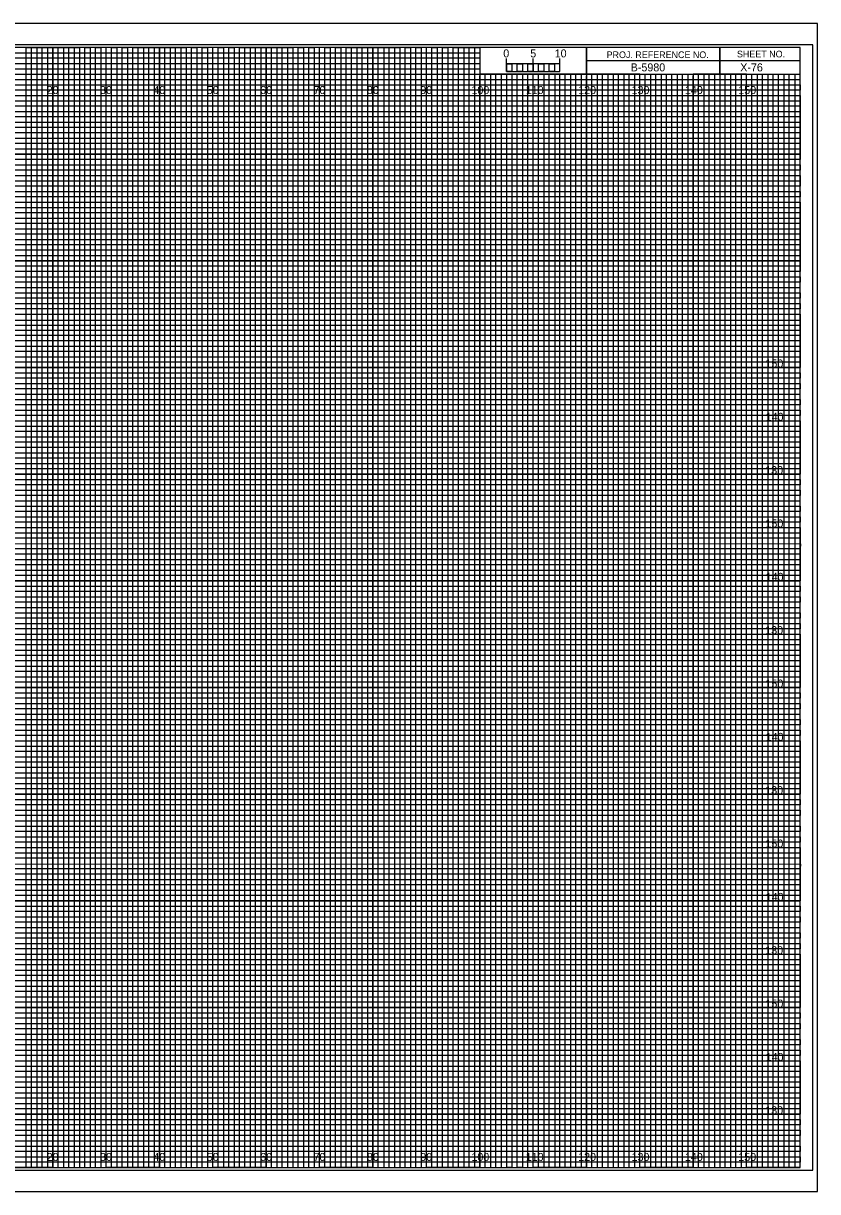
# Model space of a CAD drawing. Extents: x -13 to 323, y -5 to 654.
# Drawn here: x 174.5 to 323.3, y 435.5 to 654.5 of the extents above; entities that cross this region are included whole.
import ezdxf

# ---------------------------------------------------------------- set-up
doc = ezdxf.new("R2010")
doc.units = 0
for name, color, linetype in [('Exist Cross Section Cell', 7, 'Continuous'), ('Exist XS Center Line Elevation Label', 7, 'Continuous'), ('Exist XS Ground Line', 7, 'Continuous'), ('Prop CMT Guardrail Graphics', 7, 'Continuous'), ('Prop CMT Guardrail Widen Shoulder', 7, 'Continuous'), ('Prop CMT Pvmt Course 1', 7, 'Continuous'), ('Prop CMT Pvmt Course 2', 7, 'Continuous'), ('Prop CMT Pvmt Surface', 7, 'Continuous'), ('Prop CMT Shld Paved Course 1', 7, 'Continuous'), ('Prop CMT Shld Paved Course 2', 7, 'Continuous'), ('Prop CMT Shld Paved Course 3', 7, 'Continuous'), ('Prop CMT Slope Grass', 7, 'Continuous'), ('Prop CMT Subgrade Earthwork', 7, 'Continuous'), ('Prop Retaining Wall', 7, 'Continuous'), ('Prop XS Earthwork Shape', 7, 'Continuous')]:
    doc.layers.add(name, color=color, linetype=linetype)

msp = doc.modelspace()

# ---------------------------------------------------------------- linework, layer by layer
at = {"layer": 'Exist XS Center Line Elevation Label'}
for points in [[(165, 440), (175, 440), (175, 650), (185, 650), (185, 440), (195, 440), (195, 650), (205, 650), (205, 440), (215, 440), (215, 650), (225, 650), (225, 440), (235, 440), (235, 650), (245, 650), (245, 440), (255, 440), (255, 650), (259.93, 650), (260, 650), (260, 645), (264.99, 645), (264.99, 440), (275, 440), (275, 645), (285, 645), (285, 440), (295, 440), (295, 645), (305, 645), (305, 440), (315, 440), (315, 645)], [(0, 645), (275, 645)], [(0, 625), (320, 625), (320, 635), (0, 635)], [(0, 605), (320, 605), (320, 615), (0, 615)], [(0, 585), (320, 585), (320, 595), (0, 595)], [(0, 565), (320, 565), (320, 575), (0, 575)], [(0, 545), (320, 545), (320, 555), (0, 555)], [(0, 525), (320, 525), (320, 535), (0, 535)], [(0, 505), (320, 505), (320, 515), (0, 515)], [(0, 485), (320, 485), (320, 495), (0, 495)], [(0, 465), (320, 465), (320, 475), (0, 475)], [(0, 445), (320, 445), (320, 455), (0, 455)]]:
    msp.add_lwpolyline(points, dxfattribs=at)
at = {"layer": 'Exist XS Ground Line'}
for p, q in [((190, 650), (180, 650)), ((180, 650), (180, 440)), ((190, 440), (190, 650)), ((210, 650), (200, 650)), ((200, 650), (200, 440)), ((210, 440), (210, 650)), ((230, 650), (220, 650)), ((220, 650), (220, 440)), ((230, 440), (230, 650)), ((250, 650), (240, 650)), ((240, 650), (240, 440)), ((250, 440), (250, 650)), ((260, 650), (260, 440)), ((270, 440), (270, 645)), ((290, 645), (280, 645)), ((280, 645), (280, 440)), ((290, 440), (290, 645)), ((310, 645), (300, 645)), ((300, 645), (300, 440)), ((310, 440), (310, 645)), ((180, 440), (170, 440)), ((200, 440), (190, 440)), ((220, 440), (210, 440)), ((240, 440), (230, 440)), ((260, 440), (250, 440)), ((280, 440), (270, 440)), ((300, 440), (290, 440)), ((320, 440), (310, 440)), ((320, 440), (320, 440))]:
    msp.add_line(p, q, dxfattribs=at)
for points in [[(0, 640), (320, 640), (320, 630), (0, 630)], [(0, 620), (320, 620), (320, 610), (0, 610)], [(0, 600), (320, 600), (320, 590), (0, 590)], [(0, 580), (320, 580), (320, 570), (0, 570)], [(0, 560), (320, 560), (320, 550), (0, 550)], [(0, 540), (320, 540), (320, 530), (0, 530)], [(0, 520), (320, 520), (320, 510), (0, 510)], [(0, 500), (320, 500), (320, 490), (0, 490)], [(0, 480), (320, 480), (320, 470), (0, 470)], [(0, 460), (320, 460), (320, 450), (0, 450)]]:
    msp.add_lwpolyline(points, dxfattribs=at)
at = {"layer": 'Prop CMT Pvmt Course 1'}
for p, q in [((0, 649), (260, 649)), ((260, 649), (260, 647.98)), ((260, 647.98), (0, 647.98)), ((0, 647), (260, 647)), ((260, 647), (260, 645.89)), ((260, 645.89), (0, 645.89)), ((0, 644), (320, 644))]:
    msp.add_line(p, q, dxfattribs=at)
for points in [[(0, 643), (270, 643), (320, 643), (320, 642), (0, 642)], [(0, 641), (320, 641), (320, 639), (0, 639)], [(0, 638), (320, 638), (320, 637), (0, 636.98)], [(0, 636), (320, 636), (320, 634), (0, 634)], [(0, 633), (320, 633), (320, 632), (0, 632)], [(0, 631), (320, 631), (320, 629), (0, 629)], [(0, 628), (320, 628), (320, 627), (0, 627)], [(0, 626), (320, 626), (320, 624), (0, 624)], [(0, 623), (320, 623), (320, 622), (0, 622)], [(0, 621), (320, 621), (320, 619), (0, 619)], [(0, 618), (320, 618), (320, 617), (0, 617)], [(0, 616), (320, 616), (320, 613.95), (320, 613), (320, 612), (0, 612)], [(0, 614), (320, 614), (320, 613), (0, 613)], [(0, 611), (320, 611), (320, 609), (0, 609.03)], [(0, 609.03), (320, 609), (320, 608), (0, 608)], [(0, 607), (320, 607), (320, 606), (0, 606)], [(0, 604), (320, 604), (320, 603), (0, 603)], [(0, 602), (320, 602), (320, 601), (0, 601)], [(-0.07, 598.89), (320, 598.89), (320, 597.88), (-0.07, 597.88)], [(0, 597), (320, 597), (320, 596), (0, 596)], [(0, 594), (320, 594), (320, 593), (0, 593)], [(0, 592), (320, 592), (320, 591), (0, 591)], [(0, 589), (320, 589), (320, 588), (0, 588)], [(0, 587), (320, 587), (320, 586), (0, 586)], [(0, 584), (320, 584), (320, 583), (0, 583)], [(0, 582), (320, 582), (320, 581), (0, 581)], [(0, 579), (320, 579), (319.99, 577.98), (0, 578)], [(0, 577), (320, 577), (320, 576), (0, 576)], [(0, 574), (320, 574), (320, 573), (0, 573)], [(0, 572), (320, 572), (320, 571), (0, 571)], [(0, 569), (320, 569), (320, 568), (0, 568)], [(0, 567), (320, 567), (320, 566), (0, 566)], [(0, 564), (320, 564), (320, 563), (0, 563)], [(0, 562), (320, 562), (320, 561), (0, 561)], [(0, 559), (320, 559), (320, 558), (0, 558)], [(0, 556.99), (320.07, 556.91), (320, 556), (0, 556)], [(0, 554), (320, 554), (320, 553), (0, 553)], [(0, 552), (320, 552), (320, 551), (0, 551)], [(0, 549), (320, 549), (320, 548), (0, 548)], [(0, 547), (320, 547), (320, 546), (0, 546)], [(0, 544), (320, 544), (320, 543), (0, 543)], [(0, 542), (320, 542), (320, 541), (0, 541)], [(0, 539), (320, 539), (320, 538), (0, 538)], [(0, 537), (320, 537), (320, 536), (0, 536)], [(0, 534), (320, 534), (320, 533), (0, 533)], [(0, 532), (320, 532), (320, 531), (0, 531)], [(0, 529), (320, 529), (320, 528), (0, 528)], [(0, 527), (320, 527), (320, 526), (0, 526)], [(0, 524), (320, 524), (320, 523), (0, 523)], [(0, 522), (320, 522), (320, 521), (0, 521)], [(0, 519), (320, 519), (319.99, 517.98), (0, 518)], [(0, 517), (320, 517), (320, 516), (0, 516)], [(0, 514), (320, 514), (320, 513), (0, 513)], [(0, 512), (320, 512), (320, 511), (0, 511)], [(0, 509), (320, 509), (320, 508), (0, 508)], [(0, 507), (320, 507), (320, 506), (0, 506)], [(0, 504), (320, 504), (320, 503), (0, 503)], [(0, 502), (320, 502), (320, 501), (0, 501)], [(0, 499), (320, 499), (320, 498), (0, 498)], [(0, 496.99), (320.07, 496.91), (320, 496), (0, 496)], [(0, 494), (320, 494), (320, 493), (0, 493)], [(0, 492), (320, 492), (320, 491), (0, 491)], [(0, 489), (320, 489), (320, 488), (0, 488)], [(0, 487), (320, 487), (320, 486), (0, 486)], [(0, 484), (320, 484), (320, 483), (0, 483)], [(0, 482), (320, 482), (320, 481), (0, 481)], [(0, 479), (320, 479), (320, 478), (0, 478)], [(0, 477), (320, 477), (320, 476), (0, 476)], [(0, 474), (320, 474), (320, 473), (0, 473)], [(0, 472), (320, 472), (320, 471), (0, 471)], [(0, 469), (320, 469), (320, 468), (0, 468)], [(0, 467), (320, 467), (320, 466), (0, 466)], [(0, 464), (320, 464), (320, 463), (0, 463)], [(0, 462), (320, 462), (320, 461), (0, 461)], [(0, 459), (320, 459), (320, 458), (0, 458)], [(0, 457), (320, 457), (320, 456), (0, 456)], [(0, 454), (320, 454), (320, 453), (0, 453)], [(0, 452), (320, 452), (320, 451), (0, 451)], [(0, 449), (320, 449), (320, 448), (0, 448)], [(0, 447), (320, 447), (320, 446), (0, 446)], [(0, 444), (320, 444), (320, 443), (0, 443)], [(0, 442), (320, 442), (320, 441), (0, 441)]]:
    msp.add_lwpolyline(points, dxfattribs=at)
at = {"layer": 'Prop CMT Pvmt Surface'}
for p, q in [((267, 645), (266.01, 645)), ((266.01, 645), (266.01, 440)), ((267, 440), (267, 645)), ((269, 645), (268, 645)), ((268, 645), (268, 440)), ((269, 440), (269, 645)), ((266.01, 440), (265, 440)), ((268, 440), (267, 440))]:
    msp.add_line(p, q, dxfattribs=at)
for points in [[(175, 440), (176, 440), (176, 650), (177, 650), (177, 440)], [(177, 440), (178, 440), (178, 650), (179, 650), (179, 440)], [(180, 440), (181, 440), (181, 650), (182, 650), (182, 440)], [(182, 440), (183, 440), (183, 650), (184, 650), (184, 440)], [(185, 440), (186, 440), (186, 650), (187, 650), (187, 440)], [(187, 440), (188, 440), (188, 650), (189, 650), (189, 440)], [(190, 440), (191, 440), (191, 650), (192, 650), (192, 440)], [(192, 440), (193, 440), (193, 650), (194, 650), (194, 440)], [(195, 440), (196, 440), (196, 650), (197, 650), (197, 440)], [(197, 440), (198, 440), (198, 650), (199, 650), (199, 440)], [(200, 440), (201, 440), (201, 650), (202, 650), (202, 440)], [(202, 440), (203, 440), (203, 650), (204, 650), (204, 440)], [(205, 440), (206, 440), (206, 650), (207, 650), (207, 440)], [(207, 440), (208, 440), (208, 650), (209, 650), (209, 440)], [(210, 440), (211, 440), (211, 650), (212, 650), (212, 440)], [(212, 440), (213, 440), (213, 650), (214, 650), (214, 440)], [(215, 440), (216, 440), (216, 650), (217, 650), (217, 440)], [(217, 440), (218, 440), (218, 650), (219, 650), (219, 440)], [(220, 440), (221, 440), (221, 650), (222, 650), (222, 440)], [(222, 440), (223, 440), (223, 650), (224, 650), (224, 440)], [(225, 440), (226, 440), (226, 650), (227, 650), (227, 440)], [(227, 440), (228, 440), (228, 650), (229, 650), (229, 440)], [(230, 440), (231, 440), (231, 650), (232, 650), (232, 440)], [(232, 440), (233, 440), (233, 650), (234, 650), (234, 440)], [(235, 440), (236, 440), (236, 650), (237, 650), (237, 440)], [(237, 440), (238, 440), (238, 650), (239, 650), (239, 440)], [(240, 440), (241, 440), (241, 650), (242, 650), (242, 440)], [(242, 440), (243, 440), (243, 650), (244, 650), (244, 440)], [(245, 440), (246, 440), (246, 650), (247, 650), (247, 440)], [(247, 440), (248, 440), (248, 650), (249, 650), (249, 440)], [(250, 440), (251, 440), (251, 650), (252, 650), (252, 440)], [(252, 440), (253, 440), (253, 650), (254, 650), (254, 440)], [(255, 440), (256, 440), (256, 650), (257, 650), (257, 440)], [(257, 440), (258, 440), (258, 650), (259, 650), (259, 440)], [(260, 440), (261, 440), (261, 645), (262.02, 645), (262.02, 440)], [(262, 440), (263, 440), (263, 645), (263.99, 645), (263.99, 440)], [(270, 440), (270.98, 440), (270.98, 645), (272, 645), (272, 440)], [(272, 440), (273, 440), (273, 645), (274.05, 645), (274.05, 440)], [(275, 440), (276, 440), (276, 645), (277, 645), (277, 440)], [(277, 440), (278, 440), (278, 645), (279, 645), (279, 440)], [(280, 440), (281, 440), (281, 645), (282, 645), (282, 440)], [(282, 440), (283, 440), (283, 645), (284, 645), (284, 440)], [(285, 440), (286, 440), (286, 645), (287, 645), (287, 440)], [(287, 440), (288, 440), (288, 645), (289, 645), (289, 440)], [(290, 440), (291, 440), (291, 645), (292, 645), (292, 440)], [(292, 440), (293, 440), (293, 645), (294, 645), (294, 440)], [(295, 440), (296, 440), (296, 645), (297, 645), (297, 440)], [(297, 440), (298, 440), (298, 645), (299, 645), (299, 440)], [(300, 440), (301, 440), (301, 645), (302, 645), (302, 440)], [(302, 440), (303, 440), (303, 645), (304, 645), (304, 440)], [(305, 440), (306, 440), (306, 645), (307, 645), (307, 440)], [(307, 440), (308, 440), (308, 645), (309, 645), (309, 440)], [(310, 440), (311, 440), (311, 645), (312, 645), (312, 440)], [(312, 440), (313, 440), (313, 645), (314, 645), (314, 440)], [(315, 440), (316, 440), (316, 645), (317, 645), (317, 440)], [(317, 440), (318, 440), (318, 645), (319, 645), (319, 440)]]:
    msp.add_lwpolyline(points, dxfattribs=at)
at = {"layer": 'Prop CMT Shld Paved Course 1'}
msp.add_lwpolyline([(-10.8, 439.5), (322.4, 439.5), (322.4, 650.5), (-10.8, 650.5)], close=True, dxfattribs=at)
at = {"layer": 'Prop CMT Shld Paved Course 2'}
for p, q in [((180, 440), (180, 650)), ((190, 440), (190, 650)), ((200, 440), (200, 650)), ((210, 440), (210, 650)), ((220, 440), (220, 650)), ((230, 440), (230, 650)), ((240, 440), (240, 650)), ((250, 440), (250, 650)), ((260, 440), (260, 644.69)), ((270, 440), (270, 644.69)), ((280, 440), (280, 644.69)), ((290, 440), (290, 644.69)), ((300, 440), (300, 644.69)), ((310, 440), (310, 644.69)), ((0, 640), (320, 640)), ((0, 630), (320, 630)), ((0, 620), (320, 620)), ((0, 610), (320, 610)), ((0, 600), (320, 600)), ((0, 590), (320, 590)), ((0, 580), (320, 580)), ((0, 570), (320, 570)), ((0, 560), (320, 560)), ((0, 550), (320, 550)), ((0, 540), (320, 540)), ((0, 530), (320, 530)), ((0, 520), (320, 520)), ((0, 510), (320, 510)), ((0, 500), (320, 500)), ((0, 490), (320, 490)), ((0, 480), (320, 480)), ((0, 470), (320, 470)), ((0, 460), (320, 460)), ((0, 450), (320, 450))]:
    msp.add_line(p, q, dxfattribs=at)
at = {"layer": 'Prop CMT Shld Paved Course 3'}
for p, q in [((323.3, 654.5), (-13.4, 654.5)), ((-13.4, 435.5), (323.3, 435.5))]:
    msp.add_line(p, q, dxfattribs=at)
at = {"layer": 'Prop CMT Slope Grass'}
for p, q in [((305, 650), (305, 645)), ((305, 645), (305, 650)), ((280, 647.5), (280, 645)), ((320, 647.49), (280, 647.49)), ((280, 645), (320, 645))]:
    msp.add_line(p, q, dxfattribs=at)
for points in [[(320, 650), (0, 650), (0, 440), (320, 440)], [(280, 650), (260, 650), (260, 645.03), (280, 645.03)], [(320, 650), (280, 650), (280, 645), (320, 645)]]:
    msp.add_lwpolyline(points, close=True, dxfattribs=at)
at = {"layer": 'Prop Retaining Wall'}
for p, q in [((265, 645.49), (265, 647.9)), ((265, 646.9), (265, 647.9)), ((270, 645.49), (270, 647.9)), ((275, 645.49), (275, 647.9)), ((275, 646.9), (275, 647.9))]:
    msp.add_line(p, q, dxfattribs=at)
for points in [[(275, 646.9), (265, 646.9), (265, 645.49), (275, 645.49)], [(265, 646.9), (266, 646.9), (266, 645.49), (265, 645.49)], [(267, 646.9), (268, 646.9), (268, 645.49), (267, 645.49)], [(269, 646.9), (270, 646.9), (270, 645.49), (269, 645.49)], [(271, 646.9), (272, 646.9), (272, 645.49), (271, 645.49)], [(273, 646.9), (274, 646.9), (274, 645.49), (273, 645.49)]]:
    msp.add_lwpolyline(points, close=True, dxfattribs=at)
at = {"layer": 'Prop XS Earthwork Shape'}
msp.add_lwpolyline([(-13.4, 435.5), (323.3, 435.5), (323.3, 654.5), (-13.4, 654.5)], close=True, dxfattribs=at)

# ---------------------------------------------------------------- texts
at = {"layer": 'Exist Cross Section Cell'}
for s, p in [('20', (178.86, 641.25)), ('30', (188.86, 641.25)), ('40', (198.86, 641.25)), ('50', (208.86, 641.25)), ('60', (218.86, 641.25)), ('70', (228.86, 641.25)), ('80', (238.86, 641.25)), ('90', (248.86, 641.25)), ('100', (258.44, 641.25)), ('110', (268.62, 641.25)), ('120', (278.44, 641.25)), ('130', (288.44, 641.25)), ('140', (298.44, 641.25)), ('150', (308.44, 641.25)), ('20', (178.86, 441.25)), ('30', (188.86, 441.25)), ('40', (198.86, 441.25)), ('50', (208.86, 441.25)), ('60', (218.86, 441.25)), ('70', (228.86, 441.25)), ('80', (238.86, 441.25)), ('90', (248.86, 441.25)), ('100', (258.44, 441.25)), ('110', (268.62, 441.25)), ('120', (278.44, 441.25)), ('130', (288.44, 441.25)), ('140', (298.44, 441.25)), ('150', (308.44, 441.25))]:
    msp.add_text(s, height=1.5, dxfattribs=at).set_placement(p)
at = {"layer": 'Prop CMT Guardrail Graphics'}
msp.add_text('B-5980', height=1.5, dxfattribs=at).set_placement((288.28, 645.5))
at = {"layer": 'Prop CMT Guardrail Widen Shoulder'}
for s, p in [('5', (269.47, 648.12)), ('10', (274.04, 648.12))]:
    msp.add_text(s, height=1.5, dxfattribs=at).set_placement(p)
at = {"layer": 'Prop CMT Pvmt Course 2'}
for s, p in [('150', (313.52, 590)), ('140', (313.57, 580)), ('130', (313.49, 570)), ('150', (313.52, 560)), ('140', (313.57, 550)), ('130', (313.49, 540)), ('150', (313.52, 530)), ('140', (313.57, 520)), ('130', (313.49, 510)), ('150', (313.52, 500)), ('140', (313.57, 490)), ('130', (313.49, 480)), ('150', (313.52, 470)), ('140', (313.57, 460)), ('130', (313.49, 450))]:
    msp.add_text(s, height=1.5, dxfattribs=at).set_placement(p)
at = {"layer": 'Prop CMT Slope Grass'}
for s, p in [('PROJ. REFERENCE NO.', (283.77, 647.99)), ('SHEET NO.', (308.19, 648.12))]:
    msp.add_text(s, height=1.25, dxfattribs=at).set_placement(p)
at = {"layer": 'Prop CMT Subgrade Earthwork'}
msp.add_text('X-76', height=1.5, dxfattribs=at).set_placement((308.8, 645.5))
at = {"layer": 'Prop Retaining Wall'}
msp.add_text('0', height=1.5, dxfattribs=at).set_placement((264.41, 648.12))

doc.saveas('drawing.dxf')
